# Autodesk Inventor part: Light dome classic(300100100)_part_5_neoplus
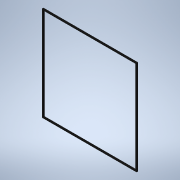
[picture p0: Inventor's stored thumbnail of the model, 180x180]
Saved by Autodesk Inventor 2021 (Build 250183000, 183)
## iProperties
Created: 2026-04
Part Number: Light dome classic(300100100)_part_5_neoplus
Material: Generic
Catalog Web Link: www.3dfindit.com
Description: Light dome classic_part_5_neoplus-
Vendor: KINGSPAN
Document SubType Name: Modeling
Designer: psAdmin
Manufacturer: KINGSPAN
Mass: 371.525 g
Surface Area: 1394.18 cm^2
Volume: 371.525 cm^3
Density: 1 g/cm^3
Appearance: PSOLRGB-128-128-128
Category: PARTsolutions
Company: KINGSPAN
Title: Light dome classic(300100100)_part_5_neoplus
Author: Cadenas PARTsolutions
PSOL_IDENT_0: {$CADENAS_DATA/23d-libs/kingspan_kla/light_dome_classic_neoplus/parts/part_5.prj},268 {VTYP=3D},{NB=
PSOL_IDENT_1: Light dome classic(300100100)_part_5_neoplus},{LINA=Light dome classic(300100100)_part_5_neoplus},{N
PSOL_IDENT_2: N=Light dome classic_part_5_neoplus},{DATE=20.03.2025 09:30:52},{GEOMDATE=21.11.2022 13:10:00},{VERS
PSOL_IDENT_3: ION=},{LINEID=10},{WBVAR=LODLEVEL,L,W},{WBNUMERIC=W}  {NB=Light dome classic(300100100)_part_5_neopl
PSOL_IDENT_4: us},{LINA=Light dome classic(300100100)_part_5_neoplus},{KT=DUMMY},{IDNR=},{PN=Light dome classic},{
PSOL_IDENT_5: LODLEVEL=300},{L=100},{W=100},{WX=100,150,200,250,300},{LX=1000},{XWX=1000}
NB: Light dome classic(300100100)_part_5_neoplus
NN: Light dome classic_part_5_neoplus
NBSYN: $PN.($LODLEVEL.$L.$W.)_part_5_neoplus
LINA: Light dome classic(300100100)_part_5_neoplus
CATALOG: Light + Air
PN: Light dome classic
LODLEVEL: 300
L: 100
W: 100
SUPPLIER: KINGSPAN
ARTICLENO: Light dome classic(300100100)_part_5_neoplus
BOMINFO: Light dome classic(300100100)_part_5_neoplus
CREATOR: CADENAS GmbH
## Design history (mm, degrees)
sketch "Sketch_1"
  geometry: L1 (-395.21, 12.944)-(-395.21, 25.446); L2 (-395.21, 25.446)-(-404.5, 25.446); L3 (-404.5, 25.446)-(-404.5, 12.944); L4 (-404.5, 12.944)-(-395.21, 12.944)
  constraints: 8 end point
extrude "Extrusion1" join sketch "Sketch_1" stored distance "d0" = 2000; taper "d1" = 0 deg
sketch "Sketch_2"
  geometry: L1 (404.5, 25.446)-(395.21, 25.446); L2 (395.21, 25.446)-(395.21, 12.944); L3 (395.21, 12.944)-(404.5, 12.944); L4 (404.5, 12.944)-(404.5, 25.446)
  constraints: 8 end point
extrude "Extrusion2" join sketch "Sketch_2" stored distance "d2" = 2000; taper "d3" = 0 deg
sketch "Sketch_3"
  geometry: L1 (404.5, 12.944)-(404.5, 25.446); L2 (404.5, 25.446)-(395.21, 25.446); L3 (395.21, 25.446)-(395.21, 12.944); L4 (395.21, 12.944)-(404.5, 12.944)
  constraints: 8 end point
extrude "Extrusion3" join sketch "Sketch_3" stored distance "d4" = 2000; taper "d5" = 0 deg
sketch "Sketch_4"
  geometry: L1 (-404.5, 25.446)-(-404.5, 12.944); L2 (-404.5, 12.944)-(-395.21, 12.944); L3 (-395.21, 12.944)-(-395.21, 25.446); L4 (-395.21, 25.446)-(-404.5, 25.446)
  constraints: 8 end point
extrude "Extrusion4" join sketch "Sketch_4" stored distance "d6" = 2000; taper "d7" = 0 deg
sketch "Sketch_5"
  geometry: L1 (-404.5, 3.096)-(-404.5, 25.446); L2 (-404.5, 25.446)-(-1396.516, 25.446); L3 (-1396.516, 25.446)-(-1396.516, 3.096); L4 (-1396.516, 3.096)-(-404.5, 3.096)
  constraints: 8 end point
extrude "Extrusion5" cut sketch "Sketch_5" stored distance "d8" = 2000; taper "d9" = 0 deg
sketch "Sketch_6"
  geometry: L1 (1396.516, 25.446)-(404.5, 25.446); L2 (404.5, 25.446)-(404.5, 3.096); L3 (404.5, 3.096)-(1396.516, 3.096); L4 (1396.516, 3.096)-(1396.516, 25.446)
  constraints: 8 end point
extrude "Extrusion6" cut sketch "Sketch_6" stored distance "d10" = 2000; taper "d11" = 0 deg
sketch "Sketch_7"
  geometry: L1 (1396.516, 25.446)-(404.5, 25.446); L2 (404.5, 25.446)-(404.5, 3.096); L3 (404.5, 3.096)-(1396.516, 3.096); L4 (1396.516, 3.096)-(1396.516, 25.446)
  constraints: 8 end point
extrude "Extrusion7" cut sketch "Sketch_7" stored distance "d12" = 2000; taper "d13" = 0 deg
sketch "Sketch_8"
  geometry: L1 (-1396.516, 25.446)-(-1396.516, 3.096); L2 (-1396.516, 3.096)-(-404.5, 3.096); L3 (-404.5, 3.096)-(-404.5, 25.446); L4 (-404.5, 25.446)-(-1396.516, 25.446)
  constraints: 8 end point
extrude "Extrusion8" cut sketch "Sketch_8" stored distance "d14" = 2000; taper "d15" = 0 deg
node "IP_5_XY"
node "IP_5_YZ"
node "IP_5_ZX"
node "IP_5_X"
node "IP_5_Y"
node "IP_5_Z"
node "IP_5_Center"
body "Solid1"
other parameters: "d16" = 0
